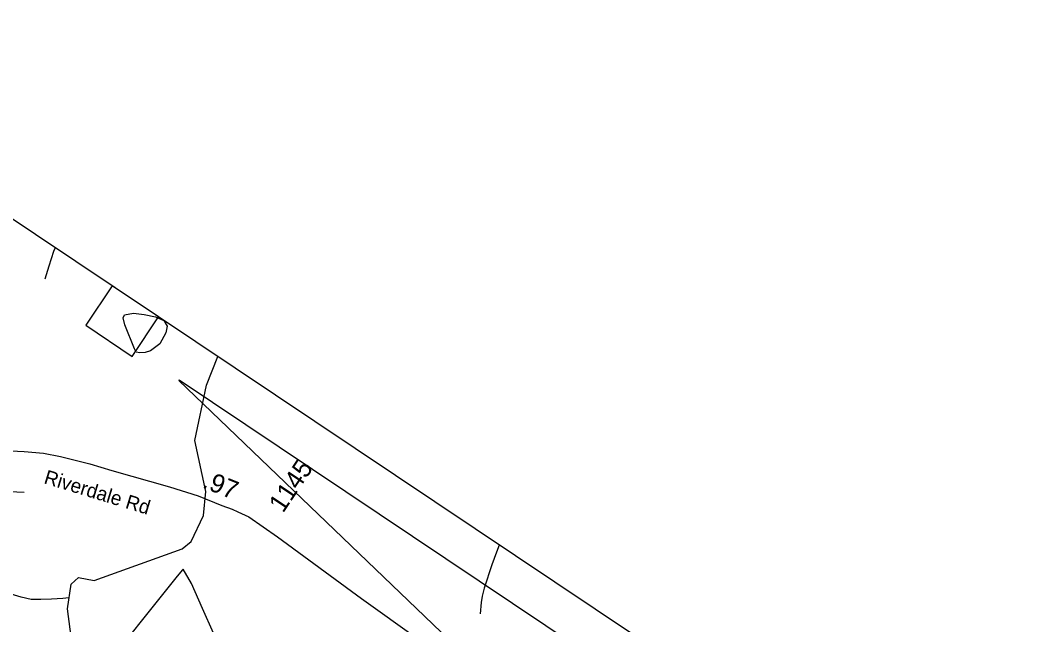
# Model space of a CAD drawing. Extents: x 1715610 to 1720914, y 798298 to 802505.
# Drawn here: x 1715932.8 to 1716081.7, y 799847.8 to 799936.1 of the extents above; entities that cross this region are included whole.
import ezdxf

# ---------------------------------------------------------------- set-up
doc = ezdxf.new("R2010")
doc.units = 0
for name, color, linetype in [('Default', 7, 'Continuous'), ('Prop DSN Text', 7, 'Continuous'), ('Prop North Arrow for Plan Sheets CELL', 7, 'Continuous')]:
    doc.layers.add(name, color=color, linetype=linetype)

msp = doc.modelspace()

# ---------------------------------------------------------------- linework, layer by layer
at = {"layer": 'Default'}
msp.add_line((1715953.01, 799892.79), (1715946.22, 799897.33), dxfattribs=at)
for points in [[(1715937.88, 799902.91), (1715937.66, 799902.37), (1715936.93, 799900.23), (1715936.35, 799898.3)], [(1715946.22, 799897.33), (1715942.37, 799891.58), (1715949.16, 799887.03), (1715953.01, 799892.79)], [(1715949.5, 799888.15), (1715948.08, 799891.65), (1715947.82, 799892.67), (1715948.02, 799893.1), (1715949.32, 799893.36), (1715950.88, 799893.16), (1715952.53, 799892.81), (1715953.76, 799892.27), (1715954.26, 799891.46), (1715954.06, 799890.47), (1715953.19, 799888.88), (1715951.82, 799887.83), (1715951.02, 799887.61), (1715950.24, 799887.57), (1715949.72, 799887.63), (1715949.5, 799888.15)], [(1715913.86, 799783.46), (1715926.83, 799784.69), (1715929.28, 799786.33), (1715932.75, 799791.41), (1715933.82, 799795.31), (1715934.49, 799803.62), (1715936.27, 799807.9), (1715940.87, 799813.98), (1715944.24, 799828.14), (1715944.4, 799831.99), (1715940.31, 799845.32), (1715939.67, 799850.14), (1715940.2, 799853.75), (1715941.31, 799854.73), (1715943.6, 799854.27), (1715956.43, 799858.9), (1715957.78, 799859.96), (1715959.57, 799863.78), (1715959.92, 799867.27), (1715958.28, 799874.75), (1715960, 799882.82), (1715961.65, 799887)], [(1715908.7, 799873.65), (1715909.93, 799873.7), (1715920.86, 799873.54), (1715922.85, 799873.5), (1715923.73, 799873.47), (1715928.54, 799873.36), (1715933.35, 799873.13), (1715936.19, 799872.9), (1715938.66, 799872.4), (1715942.93, 799871.34), (1715946.16, 799870.37), (1715954.61, 799867.94), (1715958.8, 799866.64), (1715962.26, 799865.25), (1715963.76, 799864.69), (1715964.59, 799864.33), (1715966.21, 799863.59), (1715970.39, 799860.67), (1715982.66, 799851.64), (1715991.07, 799845.64), (1716000.95, 799838.37), (1716007.03, 799833.79), (1716008.63, 799832.65)], [(1715927.54, 799867.19), (1715931.22, 799867.29), (1715933.33, 799867.18)], [(1715939.9, 799851.72), (1715938.98, 799851.62), (1715937.34, 799851.53), (1715935.78, 799851.48), (1715934.37, 799851.5), (1715932.9, 799851.82), (1715929.81, 799852.78), (1715928.67, 799853.19), (1715927.21, 799853.76), (1715922.89, 799856.6), (1715919.14, 799859.06), (1715914.64, 799861.97), (1715914.03, 799862.23)], [(1716002.81, 799859.45), (1716002.42, 799858.4), (1716001.73, 799856.54), (1716000.62, 799853.14), (1716000.3, 799851.99), (1716000.14, 799851.05), (1716000.01, 799849.4)], [(1715961.04, 799846.57), (1715959.44, 799850.2), (1715957.83, 799853.83), (1715956.57, 799855.95), (1715956.49, 799855.85), (1715955.73, 799854.9), (1715943.87, 799840.11)], [(1715961.04, 799846.57), (1715959.44, 799850.2), (1715957.83, 799853.83), (1715956.57, 799855.95), (1715956.49, 799855.85), (1715955.73, 799854.9), (1715943.87, 799840.11)]]:
    msp.add_lwpolyline(points, dxfattribs=at)
at = {"layer": 'Prop DSN Text'}
msp.add_lwpolyline([(1715972.32, 799278.02), (1716250.51, 799693.66), (1715888.23, 799936.14), (1715610.03, 799520.5)], close=True, dxfattribs=at)
at = {"layer": 'Prop North Arrow for Plan Sheets CELL'}
for p, q in [((1715956.02, 799883.59), (1715955.98, 799883.52)), ((1715956.02, 799883.59), (1715955.98, 799883.52)), ((1716006.92, 799834.63), (1715955.98, 799883.52)), ((1715956.02, 799883.59), (1716015.61, 799843.7))]:
    msp.add_line(p, q, dxfattribs=at)

# ---------------------------------------------------------------- texts
at = {"layer": 'Default'}
for s, height, rotation, p in [('1145', 2.719, 56.2051, (1715971.19, 799864.03)), ('Riverdale Rd', 2.0663, 343.1206, (1715936.11, 799868.51)), ('.97', 2.719, 338.1117, (1715959.26, 799867.92))]:
    msp.add_text(s, height=height, rotation=rotation, dxfattribs=at).set_placement(p)

doc.saveas('drawing.dxf')
